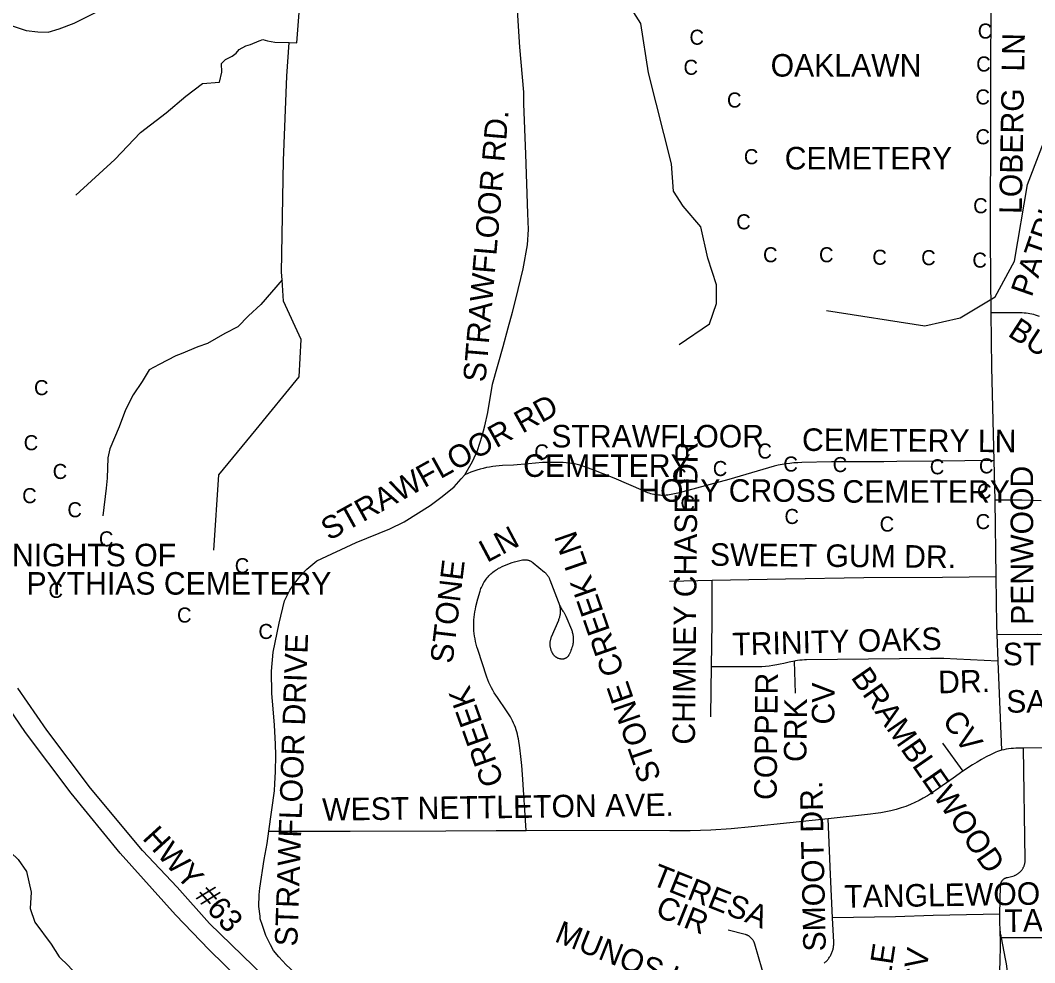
# Model space of a CAD drawing. Extents: x 1670563 to 1761545, y 515755 to 578944.
# Drawn here: x 1683746 to 1687121, y 545971 to 549107 of the extents above; entities that cross this region are included whole.
import ezdxf

# ---------------------------------------------------------------- set-up
doc = ezdxf.new("R2010")
doc.units = 0
for name, color, linetype in [('CEMETERY', 7, 'Continuous'), ('Cross', 7, 'Continuous'), ('SHP_LINE', 7, 'Continuous'), ('STREETCL', 7, 'Continuous'), ('STRNAMES', 7, 'Continuous')]:
    doc.layers.add(name, color=color, linetype=linetype)

msp = doc.modelspace()

# ---------------------------------------------------------------- linework, layer by layer
at = {"layer": 'SHP_LINE'}
for points in [[(1684640, 549033), (1684666, 549032), (1684677, 549177), (1684675, 549205), (1684677, 549228), (1684688, 549240), (1684697, 549248), (1684701, 549277), (1684809, 549364), (1684842, 549449), (1684853, 549590), (1684871, 549801), (1684890, 549885), (1684914, 549973), (1684914, 550017), (1684938, 550190), (1684843, 550198), (1684598, 550179), (1684447, 550163), (1684258, 550165)], [(1685938, 548028), (1686039, 548097), (1686062, 548165), (1686062, 548227), (1686033, 548316), (1686010, 548420), (1685951, 548489), (1685919, 548538), (1685912, 548629), (1685836, 548932), (1685810, 549096), (1685754, 549186)], [(1683930, 548525), (1684060, 548644), (1684146, 548734), (1684231, 548799), (1684296, 548855), (1684352, 548897), (1684409, 548901), (1684416, 548934), (1684415, 548963), (1684428, 548977), (1684451, 548988), (1684464, 548998), (1684474, 549010), (1684496, 549022), (1684512, 549026), (1684540, 549039), (1684553, 549043), (1684568, 549039), (1684593, 549034), (1684640, 549033)], [(1684617, 548243), (1684615, 548269), (1684621, 548640), (1684633, 548921), (1684640, 549033)], [(1686428, 548141), (1686755, 548090), (1686873, 548117), (1686989, 548187), (1687054, 548305), (1687097, 548561), (1687181, 548780)], [(1684617, 548243), (1684546, 548161), (1684505, 548124), (1684470, 548087), (1684426, 548065), (1684369, 548032), (1684336, 548021), (1684281, 547997), (1684263, 547990), (1684208, 547962), (1684175, 547944), (1684151, 547905), (1684121, 547861), (1684096, 547811), (1684075, 547754), (1684044, 547681), (1684037, 547651), (1684035, 547583), (1684031, 547550), (1684020, 547458)], [(1684390, 547344), (1684406, 547595), (1684530, 547745), (1684674, 547921), (1684680, 548045), (1684621, 548173), (1684617, 548243)], [(1683533, 546411), (1683633, 546396), (1683691, 546360), (1683739, 546315), (1683766, 546275), (1683782, 546206), (1683779, 546151), (1683794, 546106), (1683848, 546033), (1683875, 545991), (1683906, 545961), (1683972, 545888), (1683994, 545873), (1684015, 545846), (1684066, 545806), (1684093, 545779), (1684124, 545746), (1684151, 545713), (1684175, 545670), (1684208, 545622), (1684218, 545598)]]:
    msp.add_lwpolyline(points, dxfattribs=at)
at = {"layer": 'STREETCL'}
for points in [[(1683715.9, 549089.4), (1683765.2, 549073.3), (1683803.8, 549069.1), (1683838.1, 549068), (1683875.6, 549078.7), (1683924.9, 549098), (1684124.3, 549198.7), (1684179, 549218), (1684203.6, 549223.3), (1684228, 549227.9), (1684259.3, 549235.3), (1684360.1, 549244.9), (1684435.1, 549249.2), (1684540.2, 549257.8), (1684877.7, 549267.1)], [(1685224.9, 547594.7), (1685250.3, 547639.4), (1685266.7, 547675.6), (1685282.5, 547724.2), (1685291.1, 547757.9), (1685301, 547801.8), (1685317, 547895.9), (1685352.4, 548021.5), (1685368.9, 548084.2), (1685383.8, 548135.9), (1685394, 548179.1), (1685419.1, 548279.5), (1685433.3, 548359.5), (1685436.4, 548410.5), (1685434.7, 548464.6), (1685427.6, 548661.4), (1685421.3, 548829.3), (1685420.6, 548867.7), (1685408, 549017.6), (1685390.8, 549282.3)], [(1686975, 549292.9), (1686973.8, 548799.4), (1686972.5, 548376.8), (1686974.5, 548133.1)], [(1687136.4, 548121.9), (1687130.3, 548124), (1687124.1, 548125.9), (1687117.8, 548127.6), (1687111.5, 548129.1), (1687105.1, 548130.4), (1687098.7, 548131.5), (1687092.3, 548132.4), (1687085.9, 548133), (1687079.4, 548133.5), (1687072.9, 548133.7), (1687066.4, 548133.8), (1686974.5, 548133.1)], [(1686974.5, 548133.1), (1686977.2, 547952.2), (1686985.2, 547642.2)], [(1686985.3, 547642.2), (1686792.1, 547640.3), (1686661.7, 547639.2), (1686618.5, 547638.1), (1686490, 547637.4), (1686444.5, 547637.7), (1686346.6, 547635.5), (1686333.2, 547635), (1686319.9, 547634.1), (1686306.7, 547632.7), (1686293.4, 547631), (1686280.3, 547628.8), (1686267.2, 547626.3), (1686254.2, 547623.3), (1686102.7, 547578.9), (1685933.1, 547534), (1685900.4, 547527), (1685895.2, 547526.6), (1685890, 547526.3), (1685884.8, 547526.2), (1685879.6, 547526.3), (1685874.3, 547526.6), (1685869.1, 547527.1), (1685864, 547527.7), (1685858.8, 547528.5), (1685853.7, 547529.5), (1685848.6, 547530.6), (1685843.5, 547531.9), (1685838.5, 547533.4), (1685833.6, 547535.1), (1685828.7, 547536.9), (1685823.8, 547538.9), (1685819.1, 547541), (1685721.7, 547583.7), (1685648.6, 547612.8), (1685617.1, 547623.9), (1685608, 547626.5), (1685598.8, 547628.8), (1685589.5, 547630.8), (1685580.2, 547632.4), (1685570.9, 547633.7), (1685561.5, 547634.7), (1685552, 547635.4), (1685529, 547636), (1685505.9, 547635.9), (1685482.9, 547635.1), (1685459.9, 547633.5), (1685437, 547631.3), (1685386.3, 547626.5), (1685349.9, 547625.1), (1685339.1, 547624.5), (1685328.4, 547623.5), (1685317.7, 547622.2), (1685307, 547620.5), (1685296.4, 547618.5), (1685285.9, 547616.1), (1685275.4, 547613.4), (1685265.1, 547610.3), (1685254.8, 547606.9), (1685244.7, 547603.2), (1685234.7, 547599.1), (1685224.9, 547594.7)], [(1686985.2, 547642.2), (1686988.5, 547510.1)], [(1684572.8, 546409.2), (1684591.3, 546543.2), (1684593, 546567.5), (1684595.4, 546606), (1684596.1, 546661.7), (1684594.6, 546698.5), (1684591.4, 546761.3), (1684586.7, 546815.4), (1684582.8, 546867.2), (1684581.2, 546940.9), (1684587.6, 547004.4), (1684607.2, 547100.9), (1684625.3, 547175.4), (1684642.5, 547210.7), (1684654.3, 547228.8), (1684679.4, 547259.4), (1684699, 547280.5), (1684732, 547308), (1684863.4, 547369.7), (1684975.7, 547414.4), (1685023.5, 547437.9), (1685109.9, 547492.8), (1685149.1, 547522.7), (1685189.2, 547554.8), (1685212.7, 547581.5), (1685224.9, 547594.7)], [(1686988.5, 547510.1), (1686991.9, 547255.4)], [(1687143, 547508.3), (1687110.8, 547509.4), (1687078.6, 547509.8), (1686988.5, 547510.1)], [(1685428.6, 546410.7), (1685416.9, 546597.7), (1685414.6, 546627.4), (1685411.5, 546657), (1685407.6, 546686.6), (1685402.9, 546716), (1685401.4, 546723.7), (1685399.7, 546731.4), (1685397.7, 546739), (1685395.4, 546746.5), (1685392.9, 546753.9), (1685390.1, 546761.2), (1685387.1, 546768.5), (1685383.8, 546775.6), (1685380.2, 546782.6), (1685376.5, 546789.5), (1685372.5, 546796.3), (1685368.3, 546802.9), (1685363.8, 546809.4), (1685333.3, 546853.1), (1685327.9, 546861.1), (1685322.8, 546869.2), (1685318, 546877.5), (1685313.5, 546886), (1685309.2, 546894.6), (1685305.2, 546903.4), (1685301.6, 546912.3), (1685298.2, 546921.3), (1685267.7, 547013.8), (1685265, 547022.4), (1685262.6, 547031.1), (1685260.6, 547039.9), (1685258.8, 547048.8), (1685257.3, 547057.7), (1685256.2, 547066.6), (1685255.3, 547075.6), (1685254.8, 547084.6), (1685254.6, 547093.6), (1685254.7, 547102.6), (1685255.1, 547111.6), (1685255.8, 547120.6), (1685256.8, 547129.6), (1685258.1, 547138.5), (1685259.8, 547147.4), (1685261.7, 547156.2), (1685268.3, 547181.8), (1685275.6, 547207.2), (1685277.1, 547211.5), (1685278.6, 547215.8), (1685280.3, 547220.1), (1685282.2, 547224.2), (1685284.2, 547228.3), (1685286.3, 547232.4), (1685288.6, 547236.3), (1685291, 547240.2), (1685293.6, 547244), (1685296.3, 547247.7), (1685299.1, 547251.3), (1685302, 547254.8), (1685305.1, 547258.2), (1685308.2, 547261.5), (1685311.5, 547264.6), (1685314.9, 547267.7), (1685318.4, 547270.7), (1685322, 547273.5), (1685325.7, 547276.2), (1685329.5, 547278.7), (1685333.3, 547281.2), (1685337.3, 547283.5), (1685341.3, 547285.6), (1685349.2, 547289.5), (1685357.3, 547293.2), (1685365.4, 547296.6), (1685373.7, 547299.7), (1685382, 547302.6), (1685390.4, 547305.2), (1685399, 547307.6), (1685407.5, 547309.6), (1685416.2, 547311.4), (1685417.7, 547311.7), (1685419.2, 547311.9), (1685420.7, 547312.1), (1685422.2, 547312.2), (1685423.7, 547312.2), (1685425.2, 547312.2), (1685426.7, 547312.1), (1685428.2, 547312), (1685429.7, 547311.9), (1685431.2, 547311.7), (1685432.6, 547311.4), (1685434.1, 547311.1), (1685435.6, 547310.7), (1685437, 547310.3), (1685438.4, 547309.8), (1685439.8, 547309.3), (1685441.2, 547308.7), (1685442.6, 547308.1), (1685444, 547307.4), (1685445.3, 547306.7), (1685446.6, 547306), (1685447.9, 547305.2), (1685449.1, 547304.3), (1685450.3, 547303.4), (1685451.5, 547302.5), (1685452.6, 547301.5), (1685490.4, 547270.4)], [(1685490.4, 547270.4), (1685491.8, 547269.2), (1685493.1, 547268), (1685494.4, 547266.7), (1685495.7, 547265.4), (1685496.9, 547264.1), (1685498.1, 547262.7), (1685499.2, 547261.2), (1685500.3, 547259.8), (1685501.3, 547258.3), (1685502.3, 547256.7), (1685503.2, 547255.2), (1685504.1, 547253.6), (1685504.9, 547252), (1685505.7, 547250.3), (1685506.4, 547248.6), (1685507, 547246.9), (1685507.6, 547245.2), (1685541.4, 547158.2)], [(1686048, 547243.1), (1685906.1, 547239.7)], [(1686045.4, 546955.3), (1686047.3, 547104.3), (1686048.2, 547243.1)], [(1686991.9, 547255.4), (1686814.6, 547253.4), (1686552.6, 547251.4), (1686291.4, 547247.7), (1686048, 547243.1)], [(1686991.9, 547255.4), (1686994, 547095), (1686995, 547063.7)], [(1685551.1, 547141.2), (1685553.7, 547137.2), (1685556.1, 547133.1), (1685558.5, 547128.9), (1685560.7, 547124.7), (1685579.4, 547080.2), (1685580.5, 547077.1), (1685581.5, 547074.1), (1685582.4, 547071), (1685583.1, 547067.9), (1685583.8, 547064.7), (1685584.4, 547061.5), (1685584.8, 547058.4), (1685585.1, 547055.2), (1685585.4, 547051.9), (1685585.5, 547048.7), (1685585.5, 547045.5), (1685585.4, 547042.3), (1685585.2, 547039.1), (1685584.8, 547035.9), (1685584.4, 547032.7), (1685583.8, 547029.5), (1685582.6, 547024.7), (1685581.1, 547019.8), (1685579.6, 547015.1), (1685577.8, 547010.4), (1685576, 547005.7), (1685573.9, 547001.1), (1685571.8, 546996.6), (1685571.4, 546995.8), (1685571, 546995), (1685570.6, 546994.2), (1685570.2, 546993.5), (1685569.7, 546992.7), (1685569.2, 546992), (1685568.7, 546991.3), (1685568.1, 546990.6), (1685567.6, 546989.9), (1685567, 546989.2), (1685566.4, 546988.6), (1685565.7, 546988), (1685565.1, 546987.4), (1685564.4, 546986.8), (1685563.7, 546986.3), (1685563, 546985.8), (1685562.2, 546985.3), (1685561.5, 546984.8), (1685560.7, 546984.4), (1685559.9, 546984), (1685559.1, 546983.6), (1685558.3, 546983.2), (1685557.5, 546982.9), (1685556.7, 546982.6), (1685555.8, 546982.3), (1685555, 546982.1), (1685554.1, 546981.9), (1685553.3, 546981.7), (1685552.4, 546981.6), (1685551.5, 546981.4), (1685550.7, 546981.3), (1685549.8, 546981.3), (1685548.9, 546981.3), (1685548, 546981.3), (1685547.1, 546981.3), (1685546.2, 546981.4), (1685545.4, 546981.5), (1685544.5, 546981.6), (1685543.2, 546981.8), (1685541.9, 546982), (1685540.6, 546982.3), (1685539.4, 546982.7), (1685538.1, 546983.1), (1685536.9, 546983.5), (1685535.7, 546983.9), (1685534.5, 546984.5), (1685533.3, 546985), (1685532.1, 546985.6), (1685531, 546986.2), (1685529.8, 546986.9), (1685528.8, 546987.6), (1685527.7, 546988.3), (1685526.6, 546989.1), (1685525.6, 546989.9), (1685524.6, 546990.8), (1685523.7, 546991.7), (1685522.7, 546992.6), (1685521.8, 546993.5), (1685521, 546994.5), (1685520.1, 546995.5), (1685519.3, 546996.6), (1685518.6, 546997.6), (1685517.9, 546998.7), (1685517.2, 546999.8), (1685516.5, 547001), (1685515.9, 547002.1), (1685514.9, 547004.1), (1685514, 547006.1), (1685513.2, 547008.1), (1685512.4, 547010.2), (1685511.7, 547012.3), (1685511.1, 547014.4), (1685510.5, 547016.5), (1685510.1, 547018.6), (1685509.7, 547020.8), (1685509.3, 547023), (1685509.1, 547025.1), (1685508.9, 547027.3), (1685508.7, 547029.5), (1685508.7, 547031.7), (1685508.7, 547033.9), (1685508.8, 547036.1), (1685509, 547038.3), (1685509.3, 547040.5), (1685509.6, 547042.6), (1685510, 547044.8), (1685510.5, 547046.9), (1685511.1, 547049.1), (1685511.7, 547051.2), (1685512.4, 547053.3), (1685513.1, 547055.3), (1685537.1, 547111.2), (1685538.1, 547113.7), (1685539, 547116.2), (1685539.9, 547118.7), (1685540.6, 547121.3), (1685541.3, 547123.9), (1685541.8, 547126.5), (1685542.3, 547129.1), (1685542.7, 547131.7), (1685543, 547134.4), (1685543.2, 547137), (1685543.3, 547139.7), (1685543.3, 547142.3), (1685543.2, 547145), (1685543.1, 547147.7), (1685542.8, 547150.3), (1685542.4, 547153), (1685542, 547155.6), (1685541.4, 547158.2), (1685542.8, 547155.2), (1685544.3, 547152.3), (1685545.8, 547149.4), (1685547.5, 547146.6), (1685549.2, 547143.9), (1685551.1, 547141.2)], [(1686995, 547063.7), (1687131.4, 547064), (1687177, 547062)], [(1686995, 547063.7), (1686997.9, 546974.1)], [(1686321.6, 546974.9), (1686304.1, 546971.3), (1686286.7, 546967.2), (1686274.6, 546964.3), (1686262.5, 546961.8), (1686250.2, 546959.7), (1686237.9, 546958), (1686225.5, 546956.7), (1686213.2, 546955.8), (1686200.7, 546955.3), (1686045.4, 546955.3)], [(1686997.9, 546974.1), (1686861.9, 546981.7), (1686818.1, 546983.4), (1686774.2, 546983.9), (1686567.7, 546981.7), (1686361.9, 546979), (1686354.5, 546978.8), (1686347, 546978.3), (1686339.6, 546977.6), (1686332.2, 546976.7), (1686324.9, 546975.5), (1686321.6, 546974.9)], [(1686324.7, 546868.1), (1686321.6, 546974.9)], [(1686997.9, 546974.1), (1687010.4, 546677.9)], [(1686043.2, 546789.5), (1686044.5, 546879.7), (1686045.4, 546955.3)], [(1685913, 544593.8), (1685635.2, 544850.4), (1685187, 545259.7), (1684701.8, 545707), (1684475, 545915.1), (1684373.9, 546014.5), (1684262.2, 546130.7), (1684078.4, 546335.4), (1683914.6, 546534.9), (1683762.8, 546737.1), (1683648.3, 546903.8)], [(1686352, 544277.5), (1686274.8, 544347.4), (1686127.6, 544481.9), (1685917.7, 544676.6), (1685823.7, 544763.5), (1685559.2, 545005.9), (1685354.8, 545191.1), (1685211.5, 545325.6), (1685156.9, 545373.2), (1684870.9, 545637.7), (1684593.7, 545890), (1684375.3, 546101.9), (1684267.7, 546222.4), (1684152.8, 546344.9), (1683979.8, 546552.3), (1683834.5, 546745.2), (1683737.6, 546884.7)], [(1686814, 546702), (1686882.2, 546608.6)], [(1687010.4, 546677.9), (1687004, 546675.9), (1686997.7, 546673.7), (1686991.6, 546671.2), (1686975.7, 546663.8), (1686960, 546656), (1686944.5, 546647.7), (1686929.3, 546638.9), (1686914.4, 546629.7), (1686882.2, 546608.6)], [(1687004.8, 546132.6), (1687006.9, 546226.6), (1687006.9, 546227.6), (1687007, 546228.6), (1687007.1, 546229.5), (1687007.2, 546230.5), (1687007.3, 546231.5), (1687007.5, 546232.5), (1687007.7, 546233.5), (1687008, 546234.4), (1687008.2, 546235.4), (1687008.6, 546236.3), (1687008.9, 546237.3), (1687009.3, 546238.2), (1687009.7, 546239.1), (1687010.1, 546240), (1687010.6, 546240.9), (1687011.1, 546241.7), (1687011.6, 546242.6), (1687012.2, 546243.4), (1687012.8, 546244.2), (1687013.4, 546245), (1687014, 546245.7), (1687014.7, 546246.5), (1687015.4, 546247.2), (1687016.1, 546247.9), (1687016.8, 546248.6), (1687017.6, 546249.2), (1687018.4, 546249.8), (1687019.2, 546250.4), (1687020, 546251), (1687020.8, 546251.5), (1687021.7, 546252), (1687022.6, 546252.5), (1687023.4, 546252.9), (1687024.3, 546253.3), (1687025.3, 546253.7), (1687026.2, 546254.1), (1687027.1, 546254.4), (1687028.1, 546254.7), (1687029.1, 546254.9), (1687030, 546255.2), (1687052.1, 546260.8), (1687053.8, 546261.5), (1687055.6, 546262.2), (1687057.3, 546263), (1687059.1, 546263.8), (1687060.7, 546264.7), (1687062.4, 546265.6), (1687064, 546266.7), (1687065.6, 546267.7), (1687067.1, 546268.8), (1687068.6, 546270), (1687070.1, 546271.2), (1687071.5, 546272.5), (1687072.9, 546273.8), (1687074.2, 546275.2), (1687075.5, 546276.6), (1687076.7, 546278), (1687077.9, 546279.5), (1687079, 546281.1), (1687080.1, 546282.6), (1687081.1, 546284.2), (1687082.1, 546285.9), (1687083, 546287.5), (1687083.8, 546289.2), (1687084.6, 546291), (1687085.4, 546292.7), (1687086, 546294.5), (1687086.7, 546296.3), (1687087.2, 546298.1), (1687087.7, 546300), (1687088.1, 546301.8), (1687088.5, 546303.7), (1687088.8, 546305.6), (1687089, 546307.5), (1687089.2, 546309.4), (1687089.3, 546311.3), (1687089.3, 546313.2), (1687089.3, 546315.1), (1687083.5, 546685.3)], [(1687083.5, 546685.3), (1687074.8, 546685.3), (1687066.7, 546685.3), (1687058.5, 546685), (1687050.4, 546684.4), (1687042.3, 546683.6), (1687034.3, 546682.6), (1687026.3, 546681.3), (1687018.3, 546679.7), (1687010.4, 546677.9)], [(1687419.1, 546685.8), (1687083.5, 546685.3)], [(1686882.2, 546608.6), (1686849.6, 546585.7), (1686790.8, 546544.2), (1686777.5, 546535.3), (1686764, 546526.9), (1686750.2, 546518.9), (1686736.1, 546511.3), (1686721.8, 546504.2), (1686707.3, 546497.6), (1686692.6, 546491.5), (1686676.1, 546486), (1686659.5, 546481.1), (1686642.7, 546476.8), (1686625.8, 546473), (1686608.7, 546469.9), (1686591.6, 546467.4), (1686574.4, 546465.4), (1686434.1, 546450.3)], [(1686434.1, 546450.3), (1686178.8, 546422.9), (1686110.9, 546416.3), (1686042.9, 546412), (1685974.7, 546410), (1685906.5, 546410.2), (1685428.6, 546410.7)], [(1686448.4, 546120.2), (1686441.2, 546265), (1686434, 546450.3)], [(1685414.2, 545243.5), (1685368.8, 545285.1), (1684909.9, 545707.1), (1684630.7, 545963.6), (1684605.6, 545990.3), (1684588.3, 546012.2), (1684578.1, 546031.1), (1684563.2, 546061.6), (1684556.9, 546078.1), (1684551.4, 546095.4), (1684544.4, 546117.3), (1684543.6, 546126), (1684539.5, 546158.1), (1684540.3, 546197.3), (1684542.7, 546219.3), (1684557.6, 546314.2), (1684567, 546367.5), (1684572.8, 546409.2)], [(1684572.8, 546409.2), (1684843.4, 546409.2), (1685161.5, 546409.6), (1685328.8, 546410.9), (1685428.6, 546410.7)], [(1687004.8, 546132.6), (1686783.5, 546128.7), (1686658.2, 546124.1), (1686448.4, 546120.2)], [(1687005.6, 546087.5), (1687004.9, 546098.7), (1687004.6, 546110), (1687004.5, 546121.3), (1687004.8, 546132.6)], [(1686420.3, 545969.9), (1686422.6, 545971.8), (1686424.8, 545973.7), (1686426.9, 545975.7), (1686429, 545977.8), (1686431, 545979.9), (1686432.9, 545982.2), (1686434.7, 545984.4), (1686436.5, 545986.8), (1686438.2, 545989.2), (1686439.7, 545991.7), (1686441.2, 545994.2), (1686442.7, 545996.7), (1686444, 545999.3), (1686445.2, 546002), (1686446.4, 546004.7), (1686447.4, 546007.4), (1686448.3, 546010.2), (1686449.2, 546013), (1686450, 546015.8), (1686450.6, 546018.7), (1686451.2, 546021.6), (1686451.6, 546024.5), (1686452, 546027.4), (1686452.2, 546030.3), (1686452.4, 546033.2), (1686452.4, 546036.1), (1686452.4, 546039.1), (1686448.4, 546120.2)], [(1686226.8, 545906.7), (1686189.7, 546032.5), (1686189.3, 546034), (1686188.8, 546035.6), (1686188.3, 546037.1), (1686187.7, 546038.6), (1686187, 546040), (1686186.3, 546041.5), (1686185.6, 546042.9), (1686184.8, 546044.3), (1686184, 546045.6), (1686183.1, 546047), (1686182.1, 546048.3), (1686181.2, 546049.6), (1686180.2, 546050.8), (1686179.1, 546052), (1686178, 546053.2), (1686176.9, 546054.3), (1686175.7, 546055.4), (1686174.5, 546056.4), (1686173.2, 546057.4), (1686171.9, 546058.4), (1686170.6, 546059.3), (1686169.3, 546060.1), (1686167.9, 546061), (1686166.5, 546061.7), (1686165.1, 546062.5), (1686163.6, 546063.1), (1686162.1, 546063.8), (1686160.6, 546064.3), (1686159.1, 546064.9), (1686157.6, 546065.3), (1686100.9, 546079.7)], [(1686989.9, 545629.5), (1687002.9, 545901.4), (1687006.4, 545972.8), (1687006.7, 546030.2), (1687005.6, 546087.5)], [(1687010.2, 546053.8), (1687008.9, 546060.4), (1687007.7, 546067.2), (1687006.8, 546073.9), (1687006.1, 546080.7), (1687005.6, 546087.5)], [(1687824.9, 546058.5), (1687439.2, 546051.1), (1687421.7, 546051), (1687404.2, 546051.4), (1687386.7, 546052.3), (1687369.2, 546053.7), (1687361.1, 546054.6), (1687352.9, 546055.2), (1687344.7, 546055.6), (1687336.6, 546055.7), (1687328.4, 546055.6), (1687222.7, 546054), (1687010.2, 546053.8)], [(1687029.5, 545770.1), (1687034.9, 545900.1), (1687033.6, 545917.1), (1687031.8, 545934), (1687029.5, 545950.9), (1687026.7, 545967.7), (1687023.4, 545984.4), (1687010.2, 546053.8)]]:
    msp.add_lwpolyline(points, dxfattribs=at)

# ---------------------------------------------------------------- texts
at = {"layer": 'CEMETERY'}
for s, p in [('OAKLAWN', (1686242.4, 548919.7)), ('CEMETERY', (1686289.2, 548610.8)), ('STRAWFLOOR ', (1685512.6, 547685.7)), ('CEMETERY', (1685419, 547587.7)), ('HOLY CROSS', (1685801.9, 547504.8)), ('CEMETERY', (1686481.3, 547501.8)), ('KNIGHTS OF', (1683651.2, 547290.2)), ('PYTHIAS CEMETERY', (1683766.5, 547195.9))]:
    msp.add_text(s, height=75, dxfattribs=at).set_placement(p)
at = {"layer": 'Cross'}
for p in [(1686931.4, 549046.2), (1685972.2, 549025.8), (1685952.4, 548925.7), (1686926.3, 548936.6), (1686097.1, 548816.8), (1686923.8, 548827), (1686923.8, 548694.4), (1686153.3, 548628.2), (1686916.1, 548465), (1686127.8, 548411.5), (1686217.1, 548301.9), (1686403.3, 548301.9), (1686580.7, 548293.6), (1686743.1, 548292.2), (1686913.6, 548284), (1683791.4, 547859.7), (1683757, 547676.5), (1685456, 547645.9), (1686198.2, 547648.7), (1686049.9, 547590.6), (1686284.6, 547605.5), (1686448.7, 547603.8), (1686771.8, 547596.3), (1686935.3, 547599.4), (1683853.5, 547580.8), (1685914.5, 547565.5), (1683752, 547500.3), (1686929.1, 547515.2), (1685942.2, 547476.1), (1683902.5, 547453.4), (1686288.3, 547431), (1686605.1, 547405.7), (1686924.4, 547414), (1684007.3, 547356.6), (1684459.3, 547267.3), (1683839.4, 547185), (1684267.2, 547103), (1684538, 547048.4)]:
    msp.add_text('C', height=50, dxfattribs=at).set_placement(p)
at = {"layer": 'STRNAMES'}
for s, rotation, p in [('LOBERG  LN', 88.9957, (1687077.8, 548462.1)), ('STRAWFLOOR RD.', 85.1037, (1685293.5, 547901.1)), ('PATRIOT CIR', 70.731, (1687110.5, 548183.3)), ('BUNKER ', 326.9669, (1687028, 548058.7)), ('STRAWFLOOR RD', 29.0325, (1684773.1, 547374)), ('CEMETERY LN', 359.5941, (1686346.6, 547674.4)), ('CHIMNEY CHASE DR.', 89.4398, (1685990.3, 546696.5)), ('PENWOOD ', 90.159, (1687116.8, 547095.5)), ('LN', 27.9595, (1685298.7, 547301.1)), ('STONE CREEK LN', 109.1626, (1685879.1, 546586.9)), ('SWEET GUM DR.', 359.4398, (1686040.1, 547292.2)), ('STONE', 83.1765, (1685183.8, 546964.1)), ('TRINITY OAKS ', 1.5591, (1686115.7, 546993.6)), ('STRAWFLOOR DRIVE', 88.0071, (1684667.2, 546024.5)), ('STONEMILL DR.', 0.159, (1687014.8, 546960.7)), ('BRAMBLEWOOD', 304.7692, (1686507.3, 546920.6)), ('DR.', 1.5591, (1686800.5, 546867.2)), ('COPPER', 89.4398, (1686262.3, 546512.3)), ('CV', 89.4398, (1686454.1, 546763.3)), ('CREEK', 109.6448, (1685355.6, 546572.5)), ('SANTA FE', 359.8965, (1687026.2, 546803.3)), ('CRK', 89.4398, (1686361.3, 546638.6)), ('CV', 304.7692, (1686811.1, 546778)), ('SMOOT DR.', 91.2034, (1686426.2, 546009.2)), ('WEST NETTLETON AVE.', 0.8132, (1684750.5, 546443.5)), ('HWY #63', 312.2194, (1684148.8, 546383.7)), ('TERESA', 338.2613, (1685841.8, 546232.2)), ('TANGLEWOOD DR.', 0.9083, (1686487.9, 546154.1)), ('CIR', 338.2613, (1685855.2, 546127.6)), ('TANGLEWOOD DR.', 0.9083, (1687021.1, 546073.2)), ('MUNOS LN.', 338.2613, (1685519.8, 546043.1)), ('KYLE ', 81.4676, (1686619.7, 545775.1)), ('CV', 81.4676, (1686750.7, 545875.7))]:
    msp.add_text(s, height=75, rotation=rotation, dxfattribs=at).set_placement(p)

doc.saveas('drawing.dxf')
